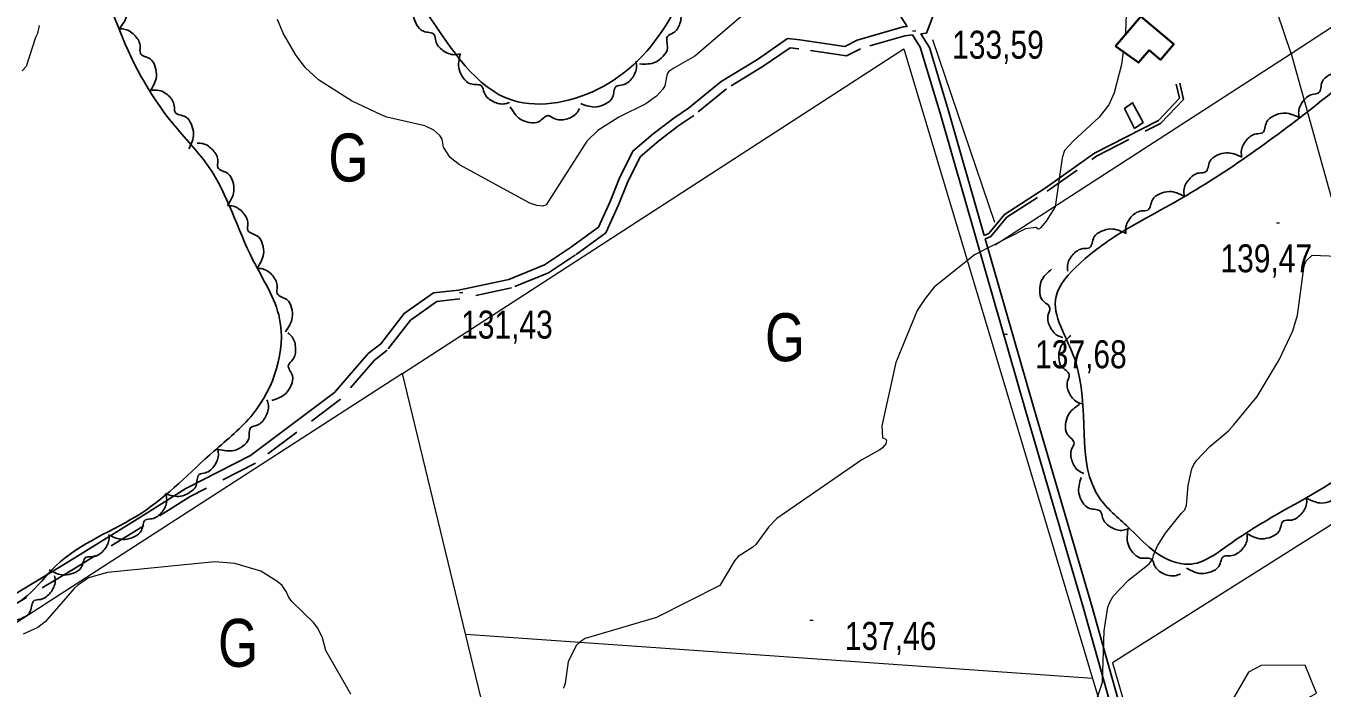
# Model space of a CAD drawing. Extents: x 483843 to 488449, y 4381269 to 4384483.
# Drawn here: x 486857.1 to 487262.3, y 4382042.2 to 4382249.2 of the extents above; entities that cross this region are included whole.
import ezdxf
from ezdxf.enums import TextEntityAlignment as Align

# ---------------------------------------------------------------- set-up
doc = ezdxf.new("R2010")
doc.units = 0
doc.header["$LTSCALE"] = 3.8
doc.linetypes.add('MEDIUM_DASHED', pattern=[4.5, 3, -1.5])
for name, color, linetype, lineweight in [('21', 7, 'Continuous', 25), ('27', 7, 'Continuous', 25), ('38', 7, 'Continuous', 25), ('47', 7, 'Continuous', 35), ('51', 7, 'Continuous', 13), ('7', 7, 'Continuous', 13), ('9', 7, 'Continuous', 13)]:
    doc.layers.add(name, color=color, linetype=linetype, lineweight=lineweight)
doc.layers.add('31', color=7, linetype='Continuous')

msp = doc.modelspace()

# ---------------------------------------------------------------- linework, layer by layer
at = {"layer": '21'}
msp.add_lwpolyline([(487203.71, 4382217.14), (487206.36, 4382219.07), (487203.09, 4382225.23), (487200.57, 4382223.37)], close=True, dxfattribs=at)
at = {"layer": '27'}
for points in [[(486286.37, 4382818.73), (486339.99, 4382829.8), (486391.37, 4382851.5), (486440.09, 4382863.84), (486483.65, 4382864.6), (486530.94, 4382876.91), (486556.13, 4382891.91), (486581.09, 4382903.76), (486654.31, 4382924.49), (486662.47, 4382925.04), (486711.17, 4382931.08), (486727.4, 4382937.04), (486766.91, 4382937.87), (486808.31, 4382909.18), (486821.81, 4382880.51), (486820.67, 4382841.64), (486812.49, 4382812.89), (486799.42, 4382770.69), (486791.78, 4382745.03), (486785, 4382714.29), (486784.58, 4382691.25), (486792.33, 4382675.66), (486812.73, 4382668.89), (486834.8, 4382649.92), (486842.09, 4382627.43), (486847.24, 4382607.13), (486841.07, 4382582.93), (486840.3, 4382544.36), (486820.33, 4382480.87), (486817.63, 4382459.06), (486815.97, 4382420.47), (486812.52, 4382387.85), (486799.99, 4382362.84), (486771.04, 4382337.85), (486733.51, 4382314.2), (486712.72, 4382296.59), (486687.38, 4382263.88), (486690.96, 4382229.15), (486713.22, 4382200.82), (486764.33, 4382192.43), (486778.5, 4382149.68), (486779.01, 4382117.89), (486787.15, 4382072.98), (486813.93, 4382065.66), (486857.54, 4382071.08), (486866.35, 4382080.34), (486893.23, 4382096.95), (486915.85, 4382116.25), (486928.06, 4382127.9), (486936.43, 4382157.7), (486928.1, 4382176.05), (486914.22, 4382205.24), (486902.98, 4382218.81), (486885.61, 4382249.79), (486879.29, 4382279.36), (486884.99, 4382315.26), (486888.52, 4382343.76), (486907.35, 4382375.88), (486922.54, 4382388.35), (486945.58, 4382366.33), (486954.28, 4382323.31), (486963.51, 4382283.6), (486982.52, 4382253.24), (487009.26, 4382225.98), (487037.6, 4382230.32), (487058.96, 4382252.37), (487069.68, 4382284.84), (487065.95, 4382338.17), (487054.24, 4382363.72), (487038.01, 4382386.56), (487027.59, 4382400.37), (487012.06, 4382422.24), (486991.9, 4382450.1), (486977.88, 4382471.56), (486976.21, 4382486.9), (486980.43, 4382521.64), (487024.88, 4382562.69), (487055.81, 4382565.06), (487106.74, 4382596.8), (487155.96, 4382614.11), (487207.74, 4382666.72), (487232.21, 4382676.6), (487267.31, 4382683.94), (487282.71, 4382693.48), (487294.56, 4382707.98), (487340.16, 4382736.84), (487389.67, 4382736.07), (487421.36, 4382716.33), (487454.29, 4382680.57), (487455.44, 4382629.06), (487501.37, 4382598.97)], [(487674.99, 4382327.12), (487600.73, 4382281.96), (487559.96, 4382263.02), (487543.94, 4382264.48), (487524.28, 4382275.4), (487514.82, 4382289.97), (487514.82, 4382303.08), (487510.45, 4382314.01), (487500.26, 4382321.29), (487492.98, 4382322.75), (487481.33, 4382316.2), (487455.84, 4382279.05), (487420.9, 4382255.74), (487361.2, 4382229.51), (487353.92, 4382233.16), (487333.53, 4382276.86), (487330.62, 4382282.69), (487326.25, 4382284.15), (487321.15, 4382280.5), (487262.18, 4382225.87), (487217.04, 4382194.55), (487186.46, 4382174.88), (487179.18, 4382164.69), (487185.01, 4382145.02), (487193.01, 4382101.31), (487202.48, 4382091.85), (487210.49, 4382084.56), (487220.68, 4382080.92), (487233.79, 4382087.47), (487262.91, 4382104.96), (487326.98, 4382145.75), (487337.9, 4382147.93), (487343, 4382145.02), (487345.91, 4382133.36), (487351.73, 4382112.24), (487364.11, 4382095.49), (487370.66, 4382086.75), (487375.76, 4382079.46), (487377.94, 4382072.18), (487375.76, 4382064.89), (487372.12, 4382058.34), (487375.03, 4382046.68), (487383.77, 4382031.39), (487391.05, 4382027.75), (487408.52, 4382034.3), (487418.71, 4382042.31), (487424.54, 4382039.4), (487429.63, 4382034.3), (487461.67, 4381974.57), (487471.13, 4381957.09), (487476.96, 4381938.88), (487483.51, 4381921.4), (487488.61, 4381921.4), (487500.26, 4381922.13), (487520.64, 4381925.04), (487535.93, 4381938.88), (487546.12, 4381962.92), (487537.39, 4382014.63), (487516.27, 4382080.19), (487500.26, 4382117.34), (487508.26, 4382137.01), (487522.1, 4382155.22), (487538.84, 4382166.87), (487551.22, 4382168.33), (487587.62, 4382141.38), (487611.65, 4382126.81), (487615.29, 4382133.36), (487617.47, 4382140.65), (487615.29, 4382155.22), (487605.83, 4382193.09), (487591.99, 4382228.79), (487597.09, 4382238.26), (487616.75, 4382255.01), (487651.69, 4382276.86), (487675.72, 4382292.16)], [(486878.6, 4382268.55), (486880.35, 4382268.24), (486883.31, 4382265.87), (486884.49, 4382262.37), (486884.33, 4382260.33), (486887.21, 4382258.24), (486888.53, 4382255.57), (486888.62, 4382252.54), (486886.19, 4382248.22)], [(486992.79, 4382240.5), (486991.03, 4382240.24), (486987.48, 4382241.56), (486985.25, 4382244.5), (486984.76, 4382246.5), (486981.37, 4382247.57), (486979.27, 4382249.69), (486978.24, 4382252.53), (486979.18, 4382257.4)], [(487060.98, 4382255.41), (487061.76, 4382253.82), (487061.57, 4382250.03), (487059.44, 4382247.02), (487057.68, 4382245.95), (487057.69, 4382242.39), (487056.3, 4382239.75), (487053.9, 4382237.91), (487048.97, 4382237.34)], [(486886.35, 4382248.29), (486888.12, 4382248.16), (486891.3, 4382246.09), (486892.83, 4382242.73), (486892.88, 4382240.68), (486895.95, 4382238.9), (486897.53, 4382236.37), (486897.92, 4382233.37), (486895.94, 4382228.82)], [(487008.28, 4382225.29), (487006.56, 4382224.84), (487002.89, 4382225.77), (487000.35, 4382228.46), (486999.65, 4382230.39), (486996.16, 4382231.08), (486993.85, 4382232.97), (486992.52, 4382235.68), (486992.93, 4382240.63)], [(487047.79, 4382238.24), (487048.02, 4382236.48), (487046.63, 4382232.94), (487043.65, 4382230.77), (487041.65, 4382230.31), (487040.52, 4382226.94), (487038.36, 4382224.88), (487035.5, 4382223.9), (487030.65, 4382224.93)], [(487255.27, 4382220.3), (487255.01, 4382222.05), (487256.33, 4382225.61), (487259.27, 4382227.84), (487261.27, 4382228.33), (487262.33, 4382231.72), (487264.46, 4382233.82), (487267.3, 4382234.86), (487272.17, 4382233.91)], [(486896.45, 4382229.11), (486898.22, 4382229.17), (486901.61, 4382227.45), (486903.49, 4382224.28), (486903.75, 4382222.24), (486907, 4382220.8), (486908.84, 4382218.45), (486909.55, 4382215.51), (486908.06, 4382210.78)], [(487030.23, 4382223.44), (487029.29, 4382221.93), (487025.98, 4382220.07), (487022.3, 4382220.27), (487020.46, 4382221.18), (487017.45, 4382219.28), (487014.48, 4382219.05), (487011.64, 4382220.1), (487008.53, 4382223.97)], [(487237.24, 4382208.2), (487237.09, 4382209.96), (487238.63, 4382213.43), (487241.71, 4382215.48), (487243.73, 4382215.84), (487245, 4382219.16), (487247.25, 4382221.12), (487250.15, 4382221.98), (487254.95, 4382220.74)], [(486910.66, 4382212.59), (486912.43, 4382212.44), (486915.6, 4382210.36), (486917.11, 4382206.99), (486917.13, 4382204.93), (486920.2, 4382203.13), (486921.76, 4382200.58), (486922.13, 4382197.58), (486920.11, 4382193.05)], [(487219.27, 4382196.06), (487219.15, 4382197.83), (487220.76, 4382201.27), (487223.87, 4382203.25), (487225.9, 4382203.58), (487227.24, 4382206.87), (487229.53, 4382208.79), (487232.45, 4382209.58), (487237.22, 4382208.24)], [(487201.02, 4382184.34), (487200.96, 4382186.11), (487202.66, 4382189.5), (487205.83, 4382191.39), (487207.87, 4382191.66), (487209.31, 4382194.91), (487211.65, 4382196.76), (487214.59, 4382197.47), (487219.32, 4382195.99)], [(486920.15, 4382193.07), (486921.92, 4382192.9), (486925.06, 4382190.77), (486926.52, 4382187.38), (486926.52, 4382185.33), (486929.55, 4382183.48), (486931.08, 4382180.92), (486931.4, 4382177.91), (486929.32, 4382173.41)], [(487182.83, 4382172.52), (487182.75, 4382174.3), (487184.43, 4382177.7), (487187.58, 4382179.62), (487189.62, 4382179.9), (487191.03, 4382183.16), (487193.36, 4382185.03), (487196.29, 4382185.76), (487201.04, 4382184.33)], [(486929.44, 4382173.46), (486931.2, 4382173.26), (486934.3, 4382171.06), (486935.69, 4382167.65), (486935.65, 4382165.59), (486938.65, 4382163.69), (486940.13, 4382161.09), (486940.4, 4382158.08), (486938.23, 4382153.62)], [(487181.31, 4382151.81), (487179.65, 4382152.45), (487177.21, 4382155.35), (487176.71, 4382159.01), (487177.27, 4382160.99), (487174.84, 4382163.59), (487174.06, 4382166.47), (487174.56, 4382169.45), (487177.78, 4382173.22)], [(486939.02, 4382153.24), (486940.3, 4382152.01), (486941.43, 4382148.39), (486940.47, 4382144.82), (486939.19, 4382143.21), (486940.42, 4382139.88), (486940.03, 4382136.92), (486938.41, 4382134.36), (486933.98, 4382132.13)], [(487187.37, 4382131.04), (487185.71, 4382131.68), (487183.26, 4382134.57), (487182.75, 4382138.22), (487183.3, 4382140.2), (487180.86, 4382142.79), (487180.07, 4382145.67), (487180.56, 4382148.66), (487183.77, 4382152.44)], [(486932.44, 4382132.39), (486932.91, 4382130.68), (486932.02, 4382126.99), (486929.36, 4382124.42), (486927.44, 4382123.7), (486926.78, 4382120.2), (486924.92, 4382117.87), (486922.22, 4382116.51), (486917.28, 4382116.86)], [(487187.9, 4382109.3), (487186.32, 4382110.1), (487184.17, 4382113.22), (487184.04, 4382116.91), (487184.79, 4382118.82), (487182.63, 4382121.65), (487182.14, 4382124.59), (487182.93, 4382127.51), (487186.5, 4382130.95)], [(486916.95, 4382117.21), (486917.28, 4382115.46), (486916.09, 4382111.86), (486913.24, 4382109.52), (486911.26, 4382108.95), (486910.32, 4382105.52), (486908.28, 4382103.35), (486905.48, 4382102.21), (486900.58, 4382102.96)], [(487275.84, 4382113.17), (487275.9, 4382111.4), (487274.18, 4382108.01), (487271.01, 4382106.12), (487268.97, 4382105.86), (487267.53, 4382102.61), (487265.19, 4382100.77), (487262.25, 4382100.06), (487257.51, 4382101.54)], [(487201.44, 4382091.88), (487199.7, 4382091.53), (487196.08, 4382092.67), (487193.7, 4382095.5), (487193.11, 4382097.46), (487189.67, 4382098.36), (487187.46, 4382100.37), (487186.29, 4382103.16), (487186.98, 4382108.07)], [(486900.98, 4382102.43), (486901.13, 4382100.66), (486899.59, 4382097.19), (486896.51, 4382095.15), (486894.49, 4382094.79), (486893.21, 4382091.47), (486890.96, 4382089.52), (486888.06, 4382088.67), (486883.26, 4382089.92)], [(487257.48, 4382101.61), (487257.49, 4382099.84), (487255.69, 4382096.5), (487252.46, 4382094.7), (487250.42, 4382094.5), (487248.89, 4382091.29), (487246.49, 4382089.51), (487243.53, 4382088.88), (487238.84, 4382090.5)], [(486883.07, 4382090.2), (486883.07, 4382088.43), (486881.25, 4382085.1), (486878.02, 4382083.32), (486875.97, 4382083.13), (486874.42, 4382079.92), (486872.02, 4382078.16), (486869.06, 4382077.55), (486864.37, 4382079.19)], [(487218.1, 4382077.92), (487216.41, 4382077.36), (487212.68, 4382078.04), (487209.97, 4382080.55), (487209.14, 4382082.43), (487205.62, 4382082.89), (487203.18, 4382084.62), (487201.67, 4382087.24), (487201.75, 4382092.2)], [(487238.94, 4382090.36), (487238.9, 4382088.58), (487237.01, 4382085.29), (487233.73, 4382083.59), (487231.69, 4382083.44), (487230.07, 4382080.27), (487227.62, 4382078.56), (487224.65, 4382078.01), (487220, 4382079.75)], [(486866.07, 4382077.32), (486866.25, 4382075.55), (486864.76, 4382072.06), (486861.72, 4382069.97), (486859.7, 4382069.58), (486858.48, 4382066.24), (486856.26, 4382064.25), (486853.37, 4382063.35), (486848.55, 4382064.52)]]:
    msp.add_spline(points, degree=3, dxfattribs=at)
at = {"layer": '38', "linetype": 'MEDIUM_DASHED'}
msp.add_line((487136.71, 4382242.62), (487134.27, 4382246.45), dxfattribs=at)
at = {"layer": '38'}
msp.add_line((487139.58, 4382242.47), (487136.85, 4382246.76), dxfattribs=at)
at = {"layer": '38', "linetype": 'MEDIUM_DASHED'}
for points in [[(487132.61, 4382249.07), (487116.04, 4382275.22), (487084.25, 4382324.31), (487059.46, 4382365.36), (487029.55, 4382412.35), (487022.36, 4382421.09), (487006.5, 4382448.62), (486987.37, 4382476.92), (486982.31, 4382484.1), (486977.9, 4382489.89), (486974.35, 4382491.77), (486968.66, 4382491.78), (486956.3, 4382490.05), (486949.27, 4382484.47), (486923.72, 4382479.74), (486913.38, 4382479.91), (486895.25, 4382480.66)], [(487142.64, 4382257.56), (487138.68, 4382246.98), (487136.85, 4382246.76)], [(487134.27, 4382246.45), (487131.9, 4382246.17), (487118, 4382242.11), (487113.65, 4382239.86), (487098.76, 4382242.1), (487096.01, 4382242.36), (487087.33, 4382236.4), (487076.09, 4382229.54), (487065.89, 4382221.26), (487061.27, 4382218.15), (487054.97, 4382213.31), (487049.13, 4382208.35), (487045.18, 4382200.33), (487042.35, 4382193.26), (487038.37, 4382184.51), (487028.92, 4382177.62), (487020.51, 4382172.09), (487008.94, 4382167.31), (486992.79, 4382163.9), (486985.59, 4382163.12), (486977.3, 4382157.29), (486970.1, 4382147.89), (486966.05, 4382144.76), (486955.5, 4382132.52), (486928.84, 4382112.52), (486908.48, 4382102.15), (486893.41, 4382092.66), (486871.98, 4382079.38), (486847.31, 4382064.58)], [(487157.05, 4382182.63), (487158.83, 4382183.37), (487163.8, 4382189.4), (487176.41, 4382197.61), (487191.81, 4382208.48), (487211.87, 4382218.77), (487218.97, 4382226.26), (487217.86, 4382231.29)]]:
    msp.add_lwpolyline(points, dxfattribs=at)
at = {"layer": '38'}
for points in [[(487132.61, 4382249.07), (487131.34, 4382248.93), (487116.95, 4382244.73), (487113.17, 4382242.77), (487099.1, 4382244.88), (487095.26, 4382245.25), (487085.8, 4382238.75), (487074.47, 4382231.84), (487064.22, 4382223.52), (487059.63, 4382220.43), (487053.21, 4382215.49), (487046.87, 4382210.11), (487042.62, 4382201.47), (487039.77, 4382194.36), (487036.12, 4382186.34), (487027.32, 4382179.93), (487019.19, 4382174.58), (487008.11, 4382170), (486992.35, 4382166.67), (486984.57, 4382165.83), (486975.33, 4382159.34), (486968.1, 4382149.89), (486964.11, 4382146.81), (486953.57, 4382134.58), (486927.35, 4382114.91), (486907.09, 4382104.59), (486891.92, 4382095.04), (486870.52, 4382081.77), (486845.78, 4382066.93)], [(487206.18, 4382001.62), (487202.44, 4382014.92), (487187.62, 4382067.49), (487169.76, 4382128.69), (487154.31, 4382182.37), (487142.91, 4382221.96), (487136.71, 4382242.62)], [(487156.74, 4382183.73), (487145.51, 4382222.72), (487139.58, 4382242.47)], [(487156.74, 4382183.73), (487158.14, 4382184.31), (487163.03, 4382190.25), (487175.77, 4382198.55), (487191.23, 4382209.45), (487211.18, 4382219.69), (487217.74, 4382226.61), (487216.76, 4382231.04)], [(487261.9, 4381817.49), (487254.14, 4381844.87), (487236.21, 4381905.92), (487220.93, 4381959.14), (487205.05, 4382015.65), (487190.22, 4382068.23), (487172.36, 4382129.44), (487157.05, 4382182.63)]]:
    msp.add_lwpolyline(points, dxfattribs=at)
at = {"layer": '47'}
msp.add_lwpolyline([(487197.77, 4382242.89), (487205.67, 4382252.21), (487215.95, 4382243.49), (487211.83, 4382238.63), (487208.26, 4382241.65), (487204.95, 4382237.75)], close=True, dxfattribs=at)
at = {"layer": '51'}
for p, q in [((487252.67, 4382240.56), (487344.67, 4382301.01)), ((487140.57, 4382245), (487159.91, 4382187.87)), ((487190.58, 4382045.26), (486994.6, 4382059))]:
    msp.add_line(p, q, dxfattribs=at)
for points in [[(487160.14, 4382180.75), (487252.72, 4382240.59), (487230.94, 4382305.05)], [(486974.89, 4382140.58), (487131.63, 4382242.03), (487198.39, 4382019.17)], [(487252.62, 4382240.93), (487289.45, 4382108.6), (487196.77, 4382050.11), (487264.44, 4381817.49)], [(486841.65, 4381991.54), (487013.57, 4381980.36), (486974.89, 4382140.58), (486805.05, 4382031.02)], [(487256.31, 4382038.23), (487260.57, 4382040.64), (487257.01, 4382049.42), (487243.29, 4382049.28), (487239.36, 4382047.25), (487234.8, 4382039.28), (487240.6, 4382030.93), (487248.19, 4382035.81)]]:
    msp.add_lwpolyline(points, dxfattribs=at)
at = {"layer": '7'}
for p, q in [((487134.31, 4382247.72), (487135.31, 4382247.72)), ((487248.07, 4382187.7), (487249.07, 4382187.7)), ((486992.69, 4382165.86), (486993.69, 4382165.86)), ((487162.99, 4382152.92), (487163.99, 4382152.92)), ((487102.24, 4382063.45), (487103.24, 4382063.45))]:
    msp.add_line(p, q, dxfattribs=at)
at = {"layer": '9'}
for points in [[(487094.93, 4382264.41), (487066.24, 4382239.76), (487059.67, 4382236.06), (487058.12, 4382234.98), (487057.83, 4382234.61), (487057.59, 4382234.21), (487056.81, 4382230.51), (487056.52, 4382229.95), (487056.15, 4382229.37), (487054.23, 4382227.24), (487050.96, 4382224.91), (487042.43, 4382220.74), (487035.88, 4382216.59), (487032.48, 4382213.22), (487019.79, 4382193.3), (487019.31, 4382193.07), (487018.89, 4382192.95), (487018.58, 4382192.93), (487017.91, 4382192.95), (487016.88, 4382193.11), (487014.62, 4382193.81), (486992.66, 4382205.83), (486989.78, 4382208.07), (486987.71, 4382211.31), (486987.21, 4382213.79), (486986.92, 4382214.39), (486986.55, 4382214.95), (486984.68, 4382216.66), (486981.86, 4382217.97), (486969.97, 4382220.75), (486968.22, 4382221.39), (486958.87, 4382225.8), (486948.56, 4382232.35), (486944.37, 4382236.28), (486941.35, 4382240.25), (486937.49, 4382246.98), (486935.77, 4382251.29)], [(487201.3, 4382258.33), (487200.92, 4382247.28), (487200.82, 4382246.48)], [(486861.25, 4382249.36), (486860.74, 4382246.85), (486860.11, 4382245.56), (486857.17, 4382236.59), (486855.91, 4382235.17)], [(487200.13, 4382241.2), (487199.61, 4382237.17), (487197.37, 4382228.31), (487195.63, 4382224.57), (487192.56, 4382220.62), (487184.67, 4382213.3), (487181.84, 4382210.26), (487181.04, 4382208.04), (487178.88, 4382192.63), (487176.04, 4382188.21), (487174.34, 4382186.11), (487173.98, 4382185.84), (487173.66, 4382185.69), (487172.9, 4382186.26), (487169.67, 4382185.82), (487153.7, 4382177.69), (487141.06, 4382167.57), (487138.25, 4382164.07), (487135.73, 4382160.27), (487129.13, 4382144.03), (487124.75, 4382124.24), (487124.96, 4382120.49), (487125.95, 4382120.06), (487126.09, 4382119.87), (487126.16, 4382119.65), (487125.91, 4382118.57), (487124.95, 4382117.33), (487124.13, 4382116.68), (487118.5, 4382113.54), (487091.84, 4382095.28), (487089.29, 4382092.5), (487085.35, 4382087.1), (487084.36, 4382086.23), (487079.83, 4382083.33), (487078.64, 4382082.06), (487074.08, 4382074.32), (487054.23, 4382064.3), (487031.95, 4382057.71), (487030.39, 4382056.7), (487029.1, 4382055.57), (487026.65, 4382050.4), (487025.72, 4382043.79), (487025.31, 4382042.42), (487025.04, 4382042.18)], [(487256.6, 4382173.55), (487256.93, 4382174.8), (487257.32, 4382175.82), (487259.23, 4382177.54), (487269.77, 4382177.19)], [(487192.11, 4382039.4), (487193.69, 4382044.08), (487194.2, 4382060.14), (487195.37, 4382067.5), (487196.11, 4382069.28), (487197.03, 4382070.93), (487201.84, 4382075.96), (487208.31, 4382081.02), (487209.47, 4382082.59), (487209.68, 4382083.78), (487210.94, 4382086.74), (487213.35, 4382090.66), (487218.44, 4382096.94), (487219.42, 4382097.95), (487219.97, 4382099.44), (487220.47, 4382105.59), (487221.62, 4382110.78), (487222.28, 4382112.12), (487223.09, 4382113.41), (487227.24, 4382117.76), (487233.09, 4382122.69), (487234.65, 4382124.41), (487242.08, 4382133.4), (487248.95, 4382144.83), (487253.17, 4382153.95), (487254.69, 4382158.77), (487256.6, 4382173.55)], [(486938.46, 4382072.4), (486937.23, 4382074.27), (486935.52, 4382075.64), (486930.55, 4382078.73), (486922.4, 4382081.18), (486916.18, 4382081.67), (486882.62, 4382078.32), (486876.71, 4382076.66), (486873.21, 4382074.27), (486872.2, 4382073.35), (486863.21, 4382063.03), (486860.8, 4382061.16), (486856.23, 4382059.05)], [(486958.73, 4382040.34), (486950.91, 4382053.97), (486949.83, 4382057.89), (486948.36, 4382060.92), (486947.02, 4382062.69), (486940.39, 4382069.15), (486939.27, 4382070.52), (486938.46, 4382072.4)]]:
    msp.add_lwpolyline(points, dxfattribs=at)

# ---------------------------------------------------------------- texts
at = {"layer": '31', "width": 0.8}
for p in [(486957.94, 4382200.59), (487094.44, 4382144.41), (486923.43, 4382048.86)]:
    msp.add_text('G', height=15, dxfattribs=at).set_placement(p, align=Align.CENTER)
at = {"layer": '7', "width": 0.8}
for s, p in [('133,59', (487146.7, 4382238.98)), ('139,47', (487230.58, 4382172.2)), ('131,43', (486993.19, 4382151.49)), ('137,68', (487172.63, 4382142.21)), ('137,46', (487113.14, 4382054.15))]:
    msp.add_text(s, height=8.75, dxfattribs=at).set_placement(p)

doc.saveas('drawing.dxf')
